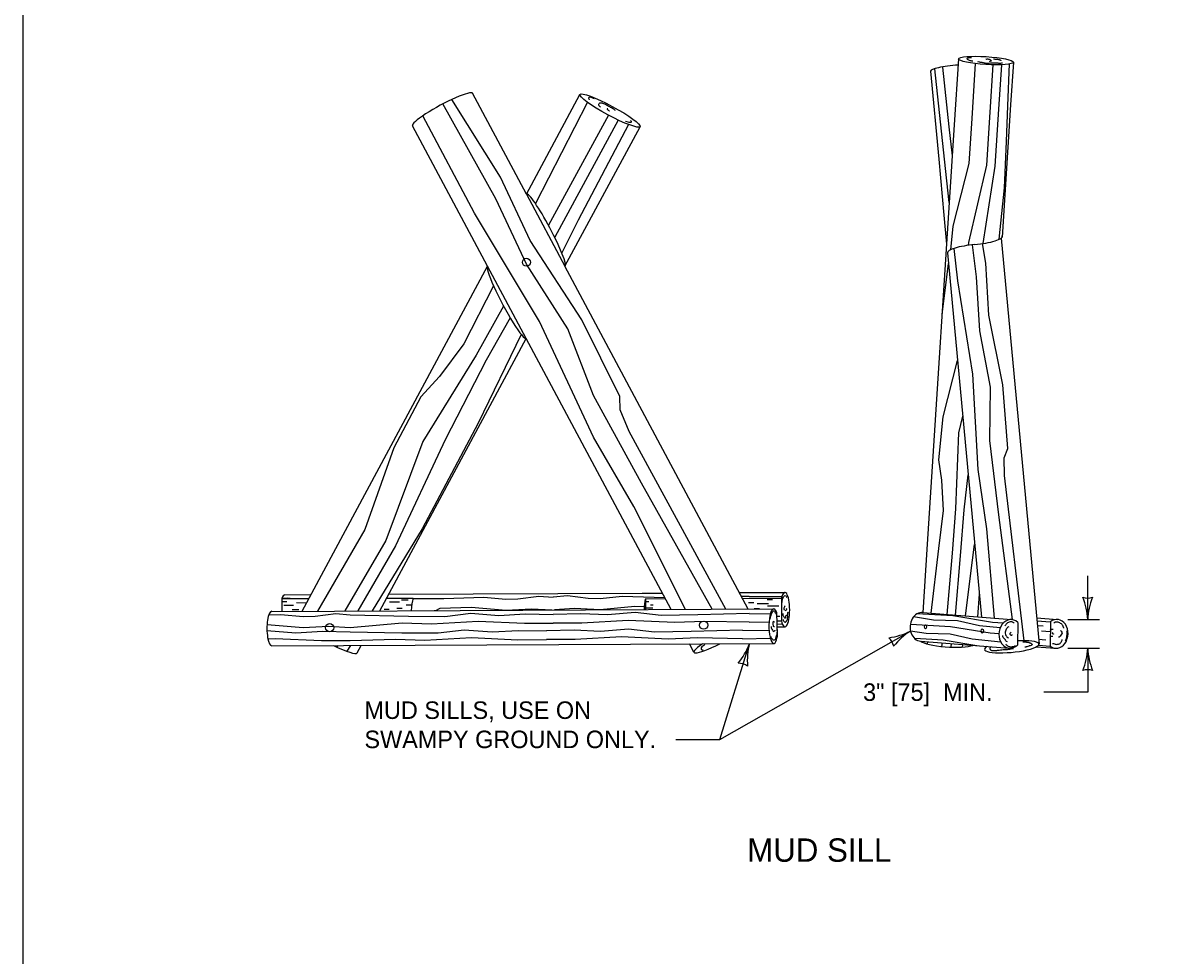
# Model space of a CAD drawing. Extents: x 49991.4 to 50021, y 49987.6 to 50011.4.
# Drawn here: x 49999.384 to 50003.324, y 49990.994 to 49994.19 of the extents above; entities that cross this region are included whole.
import ezdxf

# ---------------------------------------------------------------- set-up
doc = ezdxf.new("R2010")
doc.units = 0
for name, color, linetype in [('Level 1', 7, 'Continuous'), ('Level 2', 7, 'Continuous'), ('Level 3', 7, 'Continuous')]:
    doc.layers.add(name, color=color, linetype=linetype)

msp = doc.modelspace()

# ---------------------------------------------------------------- linework, layer by layer
at = {"layer": 'Level 1'}
for p, q in [((50002.5865, 49994.0668), (50002.5719, 49993.8405)), ((50002.7742, 49994.0552), (50002.7647, 49993.9088)), ((50002.4905, 49994.0247), (50002.5185, 49993.7235)), ((50001.107, 49993.6039), (50000.9225, 49993.949)), ((50001.107, 49993.6039), (50001.2903, 49993.9451)), ((50002.7647, 49993.9088), (50002.7352, 49993.4562)), ((50000.9741, 49993.3567), (50000.7169, 49993.8379)), ((50001.239, 49993.3564), (50001.4961, 49993.8342)), ((50002.5719, 49993.8405), (50002.4795, 49992.4044)), ((50002.5185, 49993.7235), (50002.5364, 49993.5314)), ((50001.107, 49993.6039), (50001.239, 49993.3564)), ((50002.5364, 49993.5314), (50002.5456, 49993.4324)), ((50002.7324, 49993.4528), (50002.8619, 49992.0622)), ((50002.5484, 49993.4026), (50002.6647, 49992.1548)), ((50000.339, 49992.1751), (50000.9741, 49993.3567)), ((50001.1063, 49993.1092), (50000.9741, 49993.3567)), ((50001.8666, 49992.1823), (50001.239, 49993.3566)), ((50000.605, 49992.1764), (50001.1063, 49993.1092)), ((50001.6023, 49992.1811), (50001.1063, 49993.1092)), ((50002.4795, 49992.4044), (50002.4644, 49992.1709)), ((50000.2798, 49992.2313), (50000.3694, 49992.2317)), ((50000.6354, 49992.2329), (50001.5033, 49992.237)), ((50001.5034, 49992.237), (50001.5722, 49992.2373)), ((50001.8366, 49992.2386), (50001.8516, 49992.2386)), ((50001.8516, 49992.2386), (50001.9921, 49992.2392)), ((50002.6567, 49992.2339), (50002.6518, 49992.1559)), ((50000.2698, 49992.2186), (50000.3626, 49992.219)), ((50000.2698, 49992.2187), (50000.2698, 49992.175)), ((50000.2698, 49992.2082), (50000.287, 49992.2082)), ((50000.2759, 49992.1952), (50000.3095, 49992.1952)), ((50000.3198, 49992.205), (50000.3546, 49992.2041)), ((50000.628, 49992.2192), (50000.7189, 49992.2192)), ((50000.6383, 49992.2073), (50000.6719, 49992.2073)), ((50000.6791, 49992.2145), (50000.7025, 49992.2145)), ((50000.6951, 49992.1969), (50000.7142, 49992.1969)), ((50001.5141, 49992.2178), (50001.5826, 49992.218)), ((50001.5141, 49992.2178), (50001.515, 49992.1806)), ((50001.5143, 49992.2088), (50001.5255, 49992.2088)), ((50001.5315, 49992.1969), (50001.5404, 49992.1969)), ((50001.847, 49992.219), (50001.98, 49992.2195)), ((50001.8674, 49992.2051), (50001.8856, 49992.2051)), ((50001.8972, 49992.201), (50001.9354, 49992.201)), ((50001.9317, 49992.2151), (50001.9499, 49992.2151)), ((50001.9328, 49992.1939), (50001.971, 49992.1939)), ((50001.98, 49992.2195), (50001.9798, 49992.1416)), ((50000.2348, 49992.1746), (50001.9535, 49992.1827)), ((50000.3044, 49992.1806), (50000.3283, 49992.1806)), ((50000.6195, 49992.1816), (50000.6374, 49992.1816)), ((50000.6633, 49992.185), (50000.6812, 49992.185)), ((50001.5178, 49992.1865), (50001.5403, 49992.1865)), ((50001.8862, 49992.1845), (50001.9044, 49992.1845)), ((50001.9631, 49992.1713), (50001.9658, 49992.0857)), ((50001.9635, 49992.158), (50001.9744, 49992.158)), ((50002.4643, 49992.1709), (50002.7682, 49992.1465)), ((50002.8535, 49992.1523), (50002.9255, 49992.1466)), ((50001.9647, 49992.1212), (50001.9924, 49992.1212)), ((50001.9658, 49992.1416), (50001.9798, 49992.1416)), ((50002.7893, 49992.1366), (50002.7881, 49992.0589)), ((50002.8544, 49992.1421), (50002.9009, 49992.1383)), ((50002.8559, 49992.1263), (50002.8759, 49992.1247)), ((50002.9009, 49992.1383), (50002.8995, 49992.0554)), ((50002.8603, 49992.0788), (50002.885, 49992.0768)), ((50002.8701, 49992.1078), (50002.9003, 49992.1053)), ((50000.2353, 49992.0567), (50001.9535, 49992.0647)), ((50000.5274, 49992.0321), (50000.5414, 49992.0581)), ((50001.6805, 49992.0348), (50001.6651, 49992.0634)), ((50002.4559, 49992.0725), (50002.7602, 49992.048)), ((50002.853, 49992.0532), (50002.9176, 49992.048)), ((50002.8601, 49992.0585), (50002.8995, 49992.0554))]:
    msp.add_line(p, q, dxfattribs=at)
msp.add_lwpolyline([(49999.3835, 49998.9992), (50016.7501, 49998.9992), (50016.7501, 49987.7988), (49999.3835, 49987.7988)], close=True, dxfattribs=at)
for points in [[(50002.6328, 49993.8621), (50002.6449, 49994.0507)], [(50002.6948, 49993.8841), (50002.7053, 49994.0465)], [(50002.7242, 49993.8944), (50002.734, 49994.0467)], [(50002.7551, 49993.9054), (50002.7605, 49994.0492)], [(50002.5386, 49993.7235), (50002.5049, 49994.0322)], [(50002.5542, 49993.8343), (50002.5321, 49994.0385)], [(50001.7893, 49992.1819), (50001.4585, 49992.79), (50001.4278, 49992.8651), (50001.4267, 49992.9105), (50001.2967, 49993.1725), (50001.1193, 49993.4451), (50001.0179, 49993.6619), (50000.852, 49993.9278)], [(50001.7434, 49992.1817), (50001.5013, 49992.6135), (50001.3371, 49992.9138), (50001.249, 49993.1421), (50001.1076, 49993.3631), (50001.0025, 49993.5873), (50000.8206, 49993.9123)], [(50001.3157, 49993.9181), (50001.138, 49993.571)], [(50002.6709, 49993.4343), (50002.7115, 49993.6996), (50002.7242, 49993.8944)], [(50002.7256, 49993.4488), (50002.7436, 49993.6253), (50002.7504, 49993.7837), (50002.7551, 49993.9054)], [(50001.6517, 49992.1813), (50001.4749, 49992.5336), (50001.3371, 49992.771), (50001.1518, 49993.1672), (50000.9291, 49993.5387), (50000.7518, 49993.8717)], [(50001.3874, 49993.8743), (50001.1824, 49993.4971)], [(50001.4216, 49993.857), (50001.2039, 49993.4559)], [(50002.5599, 49993.4133), (50002.5681, 49993.4935), (50002.623, 49993.7086), (50002.6328, 49993.8621)], [(50002.621, 49993.4283), (50002.6214, 49993.4384), (50002.6831, 49993.7024), (50002.6948, 49993.8841)], [(50001.4564, 49993.8418), (50001.2837, 49993.5145), (50001.2279, 49993.403)], [(50002.5651, 49993.7342), (50002.5542, 49993.8343)], [(50002.5548, 49993.5745), (50002.5386, 49993.7235)], [(50002.7096, 49992.1512), (50002.6837, 49992.4568), (50002.6541, 49992.6601), (50002.6353, 49992.9866), (50002.5839, 49993.3062), (50002.5718, 49993.4178)], [(50002.7716, 49992.1461), (50002.7244, 49992.5052), (50002.6938, 49992.7593), (50002.6959, 49992.9423), (50002.6591, 49993.1349), (50002.6482, 49993.32), (50002.6339, 49993.4299)], [(50002.8106, 49992.0741), (50002.7436, 49992.6394), (50002.7431, 49992.7003), (50002.7551, 49992.7321), (50002.7377, 49992.9501), (50002.69, 49993.189), (50002.6799, 49993.3674), (50002.6679, 49993.4339)], [(50002.5301, 49993.1915), (50002.5518, 49993.3663)], [(50000.9941, 49993.2896), (50000.8921, 49993.0904), (50000.8088, 49992.9793), (50000.7457, 49992.9092), (50000.6529, 49992.7348), (50000.5533, 49992.455), (50000.3915, 49992.1754)], [(50001.0289, 49993.2194), (50000.9351, 49993.0523), (50000.7527, 49992.7561), (50000.6252, 49992.4171), (50000.4856, 49992.1758)], [(50001.051, 49993.1804), (50000.969, 49993.0347), (50000.829, 49992.7625), (50000.6586, 49992.3989), (50000.5295, 49992.176)], [(50001.0892, 49993.1229), (50000.942, 49992.8195), (50000.7496, 49992.4574), (50000.5784, 49992.1762)], [(50002.5192, 49992.3903), (50002.5344, 49992.5197), (50002.5289, 49992.6233), (50002.5186, 49992.6931), (50002.5336, 49992.8406), (50002.5828, 49993.0334)], [(50002.5651, 49992.3741), (50002.577, 49992.5255), (50002.5869, 49992.7855), (50002.6005, 49992.8436)], [(50002.593, 49992.3642), (50002.6055, 49992.5226), (50002.6193, 49992.6423)], [(50002.4932, 49992.1686), (50002.5192, 49992.3903)], [(50002.6339, 49992.3497), (50002.6414, 49992.4038)], [(50002.5469, 49992.1643), (50002.5651, 49992.3741)], [(50002.5754, 49992.162), (50002.593, 49992.3642)], [(50002.6098, 49992.1592), (50002.6339, 49992.3497)], [(50000.5258, 49992.2336), (50000.5258, 49992.2338)], [(50000.2701, 49992.2196), (50000.2896, 49992.2204), (50000.3067, 49992.2187)], [(50000.7188, 49992.2187), (50000.8245, 49992.2182), (50000.9612, 49992.2233), (50001.037, 49992.2162), (50001.0781, 49992.2179), (50001.1489, 49992.2271), (50001.198, 49992.2226)], [(50001.5808, 49992.2212), (50001.4348, 49992.2254), (50001.3591, 49992.2175), (50001.318, 49992.2189), (50001.2471, 49992.2275), (50001.198, 49992.2226)], [(50001.8695, 49992.2256), (50001.8437, 49992.2252)], [(50001.8695, 49992.2256), (50001.9815, 49992.225)], [(50000.2248, 49992.1623), (50000.2667, 49992.1638), (50000.3425, 49992.1567), (50000.3836, 49992.1584), (50000.4544, 49992.1676), (50000.5036, 49992.1632)], [(50000.5036, 49992.1632), (50000.7029, 49992.158), (50000.828, 49992.1571), (50000.9168, 49992.1681), (50001.0124, 49992.1609), (50001.1031, 49992.1657), (50001.1982, 49992.1641)], [(50000.7908, 49992.1772), (50000.7967, 49992.1779), (50000.8114, 49992.1854), (50000.9183, 49992.1889), (50001.0371, 49992.1789), (50001.1243, 49992.1837), (50001.1937, 49992.1792)], [(50001.8698, 49992.167), (50001.6936, 49992.1624), (50001.5686, 49992.1604), (50001.4796, 49992.1706), (50001.384, 49992.1625), (50001.2935, 49992.1665), (50001.1982, 49992.1641)], [(50001.5102, 49992.1906), (50001.4779, 49992.1914), (50001.3593, 49992.1803), (50001.272, 49992.1844), (50001.2027, 49992.1792)], [(50001.8698, 49992.167), (50001.9421, 49992.1657)], [(50002.7288, 49992.1181), (50002.6578, 49992.125), (50002.5828, 49992.1426), (50002.5002, 49992.1448), (50002.4325, 49992.1556)], [(50002.7388, 49992.1341), (50002.7024, 49992.1367), (50002.5666, 49992.1587), (50002.4439, 49992.1658)], [(50000.219, 49992.1298), (50000.3427, 49992.1194), (50000.4299, 49992.1242), (50000.5038, 49992.1194)], [(50000.5038, 49992.1194), (50000.6816, 49992.1355), (50000.782, 49992.1323), (50000.9417, 49992.1411), (50001.0999, 49992.1338), (50001.1984, 49992.1342)], [(50001.8469, 49992.1105), (50001.6707, 49992.1058), (50001.5457, 49992.1038), (50001.4567, 49992.1141), (50001.3611, 49992.1059), (50001.2706, 49992.11), (50001.1753, 49992.1075)], [(50001.87, 49992.1372), (50001.7151, 49992.14), (50001.6147, 49992.136), (50001.455, 49992.1434), (50001.2969, 49992.1346), (50001.1984, 49992.1342)], [(50001.87, 49992.1372), (50001.9378, 49992.139)], [(50001.9644, 49992.1308), (50001.983, 49992.1313)], [(50002.7245, 49992.0975), (50002.6949, 49992.0997), (50002.559, 49992.1216), (50002.423, 49992.1295), (50002.4215, 49992.1297)], [(50000.2187, 49992.109), (50000.318, 49992.1015), (50000.4086, 49992.1062), (50000.5037, 49992.1046)], [(50000.2218, 49992.0802), (50000.2473, 49992.0817), (50000.4054, 49992.0743), (50000.5039, 49992.0747)], [(50000.5037, 49992.1046), (50000.68, 49992.1015), (50000.8051, 49992.1005), (50000.8939, 49992.1116), (50000.9895, 49992.1043), (50001.0802, 49992.1092), (50001.1753, 49992.1075)], [(50000.5039, 49992.0747), (50000.6587, 49992.079), (50000.7591, 49992.0758), (50000.9188, 49992.0846), (50001.077, 49992.0772), (50001.1755, 49992.0776)], [(50001.847, 49992.0806), (50001.6922, 49992.0835), (50001.5918, 49992.0795), (50001.432, 49992.0869), (50001.274, 49992.0781), (50001.1755, 49992.0776)], [(50001.8469, 49992.1105), (50001.9378, 49992.1088)], [(50001.847, 49992.0806), (50001.9417, 49992.0832)], [(50002.7307, 49992.0693), (50002.6327, 49992.079), (50002.5577, 49992.0963), (50002.4751, 49992.0987), (50002.4221, 49992.1072)], [(50002.6493, 49992.057), (50002.5339, 49992.0756), (50002.4366, 49992.0812)], [(50000.461, 49992.0578), (50000.4578, 49992.0524)], [(50000.5049, 49992.058), (50000.4925, 49992.0379)], [(50002.4806, 49992.0623), (50002.4816, 49992.0704)], [(50002.5297, 49992.0539), (50002.5312, 49992.0664)], [(50002.5613, 49992.0517), (50002.5627, 49992.0639)], [(50002.6002, 49992.0522), (50002.6012, 49992.0608)]]:
    msp.add_lwpolyline(points, dxfattribs=at)
for centre in [(50001.1069, 49993.3702), (50000.4332, 49992.1186), (50001.7138, 49992.1272)]:
    msp.add_circle(centre, 0.0139, dxfattribs=at)
for centre, major_axis, ratio, start_param, end_param in [((50002.5841, 49994.0319), (0.0936, 0.0072), 0.143064, 1.548914, 3.140392), ((50000.8198, 49993.8933), (-0.1029, -0.0554), 0.139914, 3.139201, 6.283242), ((50001.173, 49993.4801), (-0.066, 0.1238), 0.116361, 3.145361, 6.285545), ((50002.6428, 49993.4499), (0.0932, 0.0089), 0.201992, 4.679863, 6.355951), ((50002.6419, 49993.4117), (0.0934, 0.0089), 0.201542, 1.555621, 3.157543), ((50001.0402, 49993.2329), (-0.066, 0.1238), 0.116361, 0.000894, 3.157998), ((50000.2798, 49992.1723), (0, 0.059), 0.275041, 0.000018, 0.664042), ((50001.9921, 49992.1802), (0, 0.059), 0.275041, 2.285093, 7.125252), ((50000.729, 49992.1729), (0, 0.059), 0.275041, 0.667259, 1.502637), ((50001.5261, 49992.1781), (0, 0.059), 0.275041, 0.832502, 1.528499), ((50000.2348, 49992.1157), (0, 0.059), 0.275041, 0.000018, 3.17879), ((50001.9535, 49992.1237), (0, 0.059), 0.275041, 5.650695, 10.294257), ((50002.4604, 49992.1217), (0.0039, 0.0492), 0.803113, 6.282757, 9.424573), ((50002.7642, 49992.0973), (0.0039, 0.0492), 0.803113, 5.697673, 10.16742), ((50002.9216, 49992.0973), (0.0039, 0.0492), 0.803113, 2.649394, 6.932864), ((50002.7682, 49992.0533), (0.0932, 0.0089), 0.201992, 2.665922, 7.614822), ((50000.4245, 49992.0874), (-0.1029, 0.0554), 0.139914, 1.86222, 3.141392), ((50001.7836, 49992.0897), (-0.1029, -0.0554), 0.139914, 5.440424, 7.640142), ((50002.5487, 49992.0706), (-0.0937, 0.0061), 0.194104, 0.229025, 2.752598)]:
    msp.add_ellipse(centre, major_axis=major_axis, ratio=ratio, start_param=start_param, end_param=end_param, dxfattribs=at)
for centre, major_axis, ratio in [((50002.6803, 49994.061), (0.0937, -0.0058), 0.143064), ((50001.3932, 49993.8897), (-0.1029, 0.0554), 0.139914), ((50002.4729, 49992.1216), (0, 0.00692), 0.506883), ((50002.6678, 49992.1073), (0, 0.00692), 0.506883)]:
    msp.add_ellipse(centre, major_axis=major_axis, ratio=ratio, dxfattribs=at)
for points in [[(50002.6349, 49994.0587), (50002.6294, 49994.0598), (50002.6236, 49994.0611), (50002.6193, 49994.0638), (50002.6163, 49994.0664), (50002.6168, 49994.0696), (50002.6208, 49994.0705), (50002.6252, 49994.0715), (50002.6311, 49994.0711)], [(50002.6519, 49994.057), (50002.6572, 49994.057), (50002.66, 49994.056), (50002.6659, 49994.0553), (50002.6708, 49994.0541), (50002.6765, 49994.0532), (50002.6831, 49994.0521), (50002.6866, 49994.0521), (50002.6962, 49994.0528), (50002.6963, 49994.0528), (50002.7024, 49994.0532), (50002.7097, 49994.0528), (50002.7204, 49994.0528), (50002.7264, 49994.0517), (50002.7316, 49994.0521), (50002.7364, 49994.0534)], [(50002.6919, 49994.0578), (50002.6974, 49994.0595), (50002.6989, 49994.0598), (50002.6963, 49994.0626), (50002.6953, 49994.0633), (50002.69, 49994.0648), (50002.6848, 49994.0654), (50002.6805, 49994.0654), (50002.68, 49994.0659)], [(50002.7063, 49994.0672), (50002.7086, 49994.0664), (50002.712, 49994.0661), (50002.7163, 49994.0654), (50002.7204, 49994.0653), (50002.7256, 49994.0641), (50002.7278, 49994.0638), (50002.7302, 49994.0623), (50002.7311, 49994.0609), (50002.7316, 49994.0598), (50002.7316, 49994.0595)], [(50001.34, 49993.9298), (50001.3325, 49993.9331), (50001.3243, 49993.9352), (50001.3203, 49993.9335), (50001.3197, 49993.932), (50001.3213, 49993.9277), (50001.3219, 49993.9263)], [(50001.4119, 49993.8896), (50001.4042, 49993.8954), (50001.392, 49993.902), (50001.3806, 49993.9087), (50001.369, 49993.914), (50001.3626, 49993.9155), (50001.3572, 49993.9146), (50001.3547, 49993.9121), (50001.3542, 49993.9088), (50001.3558, 49993.9062), (50001.3602, 49993.9016)], [(50001.3859, 49993.8954), (50001.384, 49993.8959), (50001.3837, 49993.8948), (50001.386, 49993.892), (50001.3874, 49993.891), (50001.3899, 49993.8888), (50001.3912, 49993.8891)], [(50001.4634, 49993.8552), (50001.4655, 49993.8529), (50001.4654, 49993.8504), (50001.4627, 49993.8488), (50001.4556, 49993.8495), (50001.4466, 49993.8527)], [(50001.9813, 49992.1951), (50001.9813, 49992.2032), (50001.9822, 49992.2059), (50001.9834, 49992.2135), (50001.9845, 49992.2181), (50001.9876, 49992.2243), (50001.9908, 49992.2281), (50001.995, 49992.2281), (50001.9973, 49992.2246), (50001.9984, 49992.2226)], [(50001.9927, 49992.1934), (50001.991, 49992.1913), (50001.9893, 49992.1875), (50001.9885, 49992.1826), (50001.9899, 49992.1783)], [(50001.9424, 49992.1496), (50001.9424, 49992.1518), (50001.9424, 49992.1542), (50001.9432, 49992.1585), (50001.9446, 49992.1601), (50001.9452, 49992.1629), (50001.9455, 49992.1653), (50001.9469, 49992.1683), (50001.9489, 49992.1715), (50001.9503, 49992.1748), (50001.9529, 49992.1761), (50001.9552, 49992.1759), (50001.9569, 49992.1734), (50001.9577, 49992.1712), (50001.9594, 49992.1683), (50001.9611, 49992.1648)], [(50001.9842, 49992.1683), (50001.9845, 49992.1637), (50001.9854, 49992.16), (50001.9879, 49992.1559), (50001.9905, 49992.1529), (50001.9925, 49992.1521), (50001.9939, 49992.1524), (50001.9948, 49992.1554), (50001.9968, 49992.1616)], [(50001.9856, 49992.1466), (50001.9865, 49992.1442), (50001.9879, 49992.1409), (50001.9902, 49992.1393), (50001.9936, 49992.1377), (50001.9947, 49992.1388), (50001.9976, 49992.1415), (50001.9976, 49992.1421), (50001.9993, 49992.1447), (50002.0007, 49992.1496), (50002.0016, 49992.155), (50002.0013, 49992.1599), (50002.003, 49992.1726)], [(50001.9967, 49992.1848), (50001.9973, 49992.1826), (50001.9959, 49992.1783), (50001.995, 49992.1772), (50001.9933, 49992.1769)], [(50001.9444, 49992.1226), (50001.9452, 49992.1183), (50001.9489, 49992.1097), (50001.9523, 49992.1059), (50001.9575, 49992.1085), (50001.9589, 49992.1102)], [(50001.9563, 49992.137), (50001.9546, 49992.1389), (50001.9518, 49992.1391), (50001.9509, 49992.1375), (50001.9506, 49992.1364), (50001.9504, 49992.1334), (50001.9501, 49992.1307), (50001.9512, 49992.1275), (50001.9515, 49992.1251), (50001.9523, 49992.1226), (50001.9538, 49992.1221), (50001.9563, 49992.1229)], [(50002.7768, 49992.1338), (50002.7739, 49992.1362), (50002.7707, 49992.1377), (50002.768, 49992.1384), (50002.7631, 49992.1383), (50002.7571, 49992.1364), (50002.752, 49992.1327), (50002.748, 49992.1289), (50002.7446, 49992.1238)], [(50002.7591, 49992.1213), (50002.7528, 49992.118), (50002.7499, 49992.113), (50002.7469, 49992.1065), (50002.746, 49992.0999), (50002.7487, 49992.092), (50002.7522, 49992.0874), (50002.7572, 49992.0829)], [(50002.9004, 49992.1101), (50002.9005, 49992.1102), (50002.9043, 49992.1129), (50002.9073, 49992.1134), (50002.9099, 49992.1135)], [(50002.9127, 49992.1358), (50002.9185, 49992.1381), (50002.9232, 49992.1389), (50002.9282, 49992.1379), (50002.9348, 49992.1344), (50002.9396, 49992.1303), (50002.9419, 49992.1267), (50002.9448, 49992.1209), (50002.9456, 49992.1175)], [(50001.965, 49992.1121), (50001.9649, 49992.1077), (50001.9649, 49992.1045), (50001.964, 49992.0964), (50001.9634, 49992.0926), (50001.9614, 49992.0877), (50001.96, 49992.0831), (50001.9595, 49992.0791), (50001.9552, 49992.0758), (50001.9518, 49992.0761), (50001.9495, 49992.0791), (50001.9469, 49992.0818), (50001.9444, 49992.085), (50001.9444, 49992.0861), (50001.9444, 49992.0888)], [(50002.7538, 49992.0698), (50002.7487, 49992.0739), (50002.7466, 49992.0771), (50002.7433, 49992.0807), (50002.7396, 49992.0853), (50002.738, 49992.092)], [(50002.7665, 49992.1027), (50002.7622, 49992.0991), (50002.7624, 49992.0961), (50002.7641, 49992.0941), (50002.7666, 49992.0927), (50002.7689, 49992.0935), (50002.7698, 49992.0949)], [(50002.9086, 49992.0879), (50002.9059, 49992.0886), (50002.9026, 49992.0893), (50002.9001, 49992.0903)], [(50002.9096, 49992.1016), (50002.9077, 49992.1003), (50002.9076, 49992.0989), (50002.9086, 49992.0979), (50002.9108, 49992.0974), (50002.9118, 49992.0969)], [(50002.9083, 49992.0647), (50002.915, 49992.0633), (50002.9193, 49992.0619), (50002.9254, 49992.0616), (50002.9311, 49992.0628), (50002.9338, 49992.0648), (50002.9374, 49992.0685), (50002.9402, 49992.0736), (50002.9413, 49992.0779)], [(50002.9356, 49992.1093), (50002.9398, 49992.1034), (50002.9406, 49992.0999), (50002.937, 49992.093), (50002.932, 49992.0872), (50002.9291, 49992.086)], [(50002.9517, 49992.074), (50002.9532, 49992.0765), (50002.9556, 49992.0815), (50002.9567, 49992.0862), (50002.9585, 49992.0944), (50002.9585, 49992.1016), (50002.9566, 49992.1073)], [(50001.7175, 49992.0606), (50001.7111, 49992.0556), (50001.7055, 49992.0493), (50001.7049, 49992.045), (50001.7062, 49992.0437), (50001.7107, 49992.0432), (50001.7122, 49992.0431)], [(50002.6986, 49992.0519), (50002.6963, 49992.0509), (50002.6937, 49992.0488), (50002.693, 49992.0466), (50002.6942, 49992.0445), (50002.6955, 49992.0424), (50002.6979, 49992.0414), (50002.7012, 49992.0405), (50002.707, 49992.0403), (50002.7153, 49992.0403), (50002.7201, 49992.0411), (50002.7256, 49992.0416), (50002.735, 49992.0431), (50002.7434, 49992.0437), (50002.75, 49992.0442), (50002.7574, 49992.0448), (50002.7663, 49992.0463), (50002.7745, 49992.0476)], [(50002.7553, 49992.0489), (50002.752, 49992.0488), (50002.7492, 49992.0488), (50002.7483, 49992.0488)], [(50002.7803, 49992.0561), (50002.7766, 49992.0544), (50002.7701, 49992.0525), (50002.7676, 49992.0522), (50002.7622, 49992.0528), (50002.7577, 49992.0543), (50002.7529, 49992.0571), (50002.7495, 49992.0602), (50002.7484, 49992.0623)], [(50002.8069, 49992.0702), (50002.8115, 49992.0702), (50002.816, 49992.0702), (50002.8192, 49992.0695), (50002.8222, 49992.0688), (50002.8269, 49992.0681), (50002.8293, 49992.0672), (50002.833, 49992.066), (50002.8344, 49992.0652), (50002.8356, 49992.0641), (50002.8372, 49992.0626), (50002.838, 49992.0604), (50002.8374, 49992.0593), (50002.8349, 49992.0578), (50002.8293, 49992.0562), (50002.8275, 49992.0556), (50002.8207, 49992.0535), (50002.8183, 49992.053), (50002.8152, 49992.0519), (50002.8138, 49992.0519)]]:
    msp.add_spline(points, degree=3, dxfattribs=at)
at = {"layer": 'Level 3'}
for p, q in [((50003.0286, 49992.1466), (50003.0286, 49992.2966)), ((50002.9602, 49992.1466), (50003.0686, 49992.1466)), ((50001.7686, 49991.7361), (50001.8704, 49992.0644)), ((50002.9602, 49992.0479), (50003.0686, 49992.0479))]:
    msp.add_line(p, q, dxfattribs=at)
for points in [[(50001.6186, 49991.7361), (50001.7686, 49991.7361), (50002.4221, 49992.1072)], [(50003.0286, 49992.0479), (50003.0286, 49991.8979), (50002.8786, 49991.8979)]]:
    msp.add_lwpolyline(points, dxfattribs=at)
for centre, radius, start, end in [((50003.0286, 49992.2748), 0.0548, 252.1388, 287.8612), ((50002.7959, 49992.1351), 0.233, 2.8273, 22.0772), ((50003.2507, 49992.1374), 0.2223, 157.456, 177.6395), ((50002.3203, 49992.3049), 0.2223, 277.049, 297.2325), ((50002.3106, 49992.0439), 0.0548, 11.7318, 47.4542), ((50002.547, 49991.9105), 0.233, 122.4203, 141.6702), ((50001.661, 49992.1389), 0.2223, 320.2254, 340.4089), ((50002.0961, 49992.0064), 0.233, 165.5967, 184.8465), ((50002.8064, 49992.0571), 0.2223, 337.456, 357.6395), ((50003.2613, 49992.0594), 0.233, 182.8273, 202.0772), ((50001.8324, 49991.9419), 0.0548, 54.9082, 90.6306), ((50003.0286, 49991.9197), 0.0548, 72.1388, 107.8612)]:
    msp.add_arc(centre, radius, start, end, dxfattribs=at)

# ---------------------------------------------------------------- texts
at = {"layer": 'Level 2'}
msp.add_text('3" [75]  MIN.', height=0.06, rotation=359.9993, dxfattribs=at).set_placement((50002.2596, 49991.8679))
for s, height, p in [('MUD SILLS, USE ON ', 0.06, (50000.5524, 49991.8061)), ('SWAMPY GROUND ONLY.', 0.06, (50000.5524, 49991.7061)), ('MUD SILL', 0.08, (50001.8628, 49991.3169))]:
    msp.add_text(s, height=height, dxfattribs=at).set_placement(p)

doc.saveas('drawing.dxf')
